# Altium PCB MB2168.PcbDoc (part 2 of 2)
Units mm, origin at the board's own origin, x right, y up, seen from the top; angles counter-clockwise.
Board outline 43 x 47 mm, 2 copper layers (Top Layer, Bottom Layer), stack 0.996 mm thick; 88 components, 71 nets, 358 pads, 587 vias.
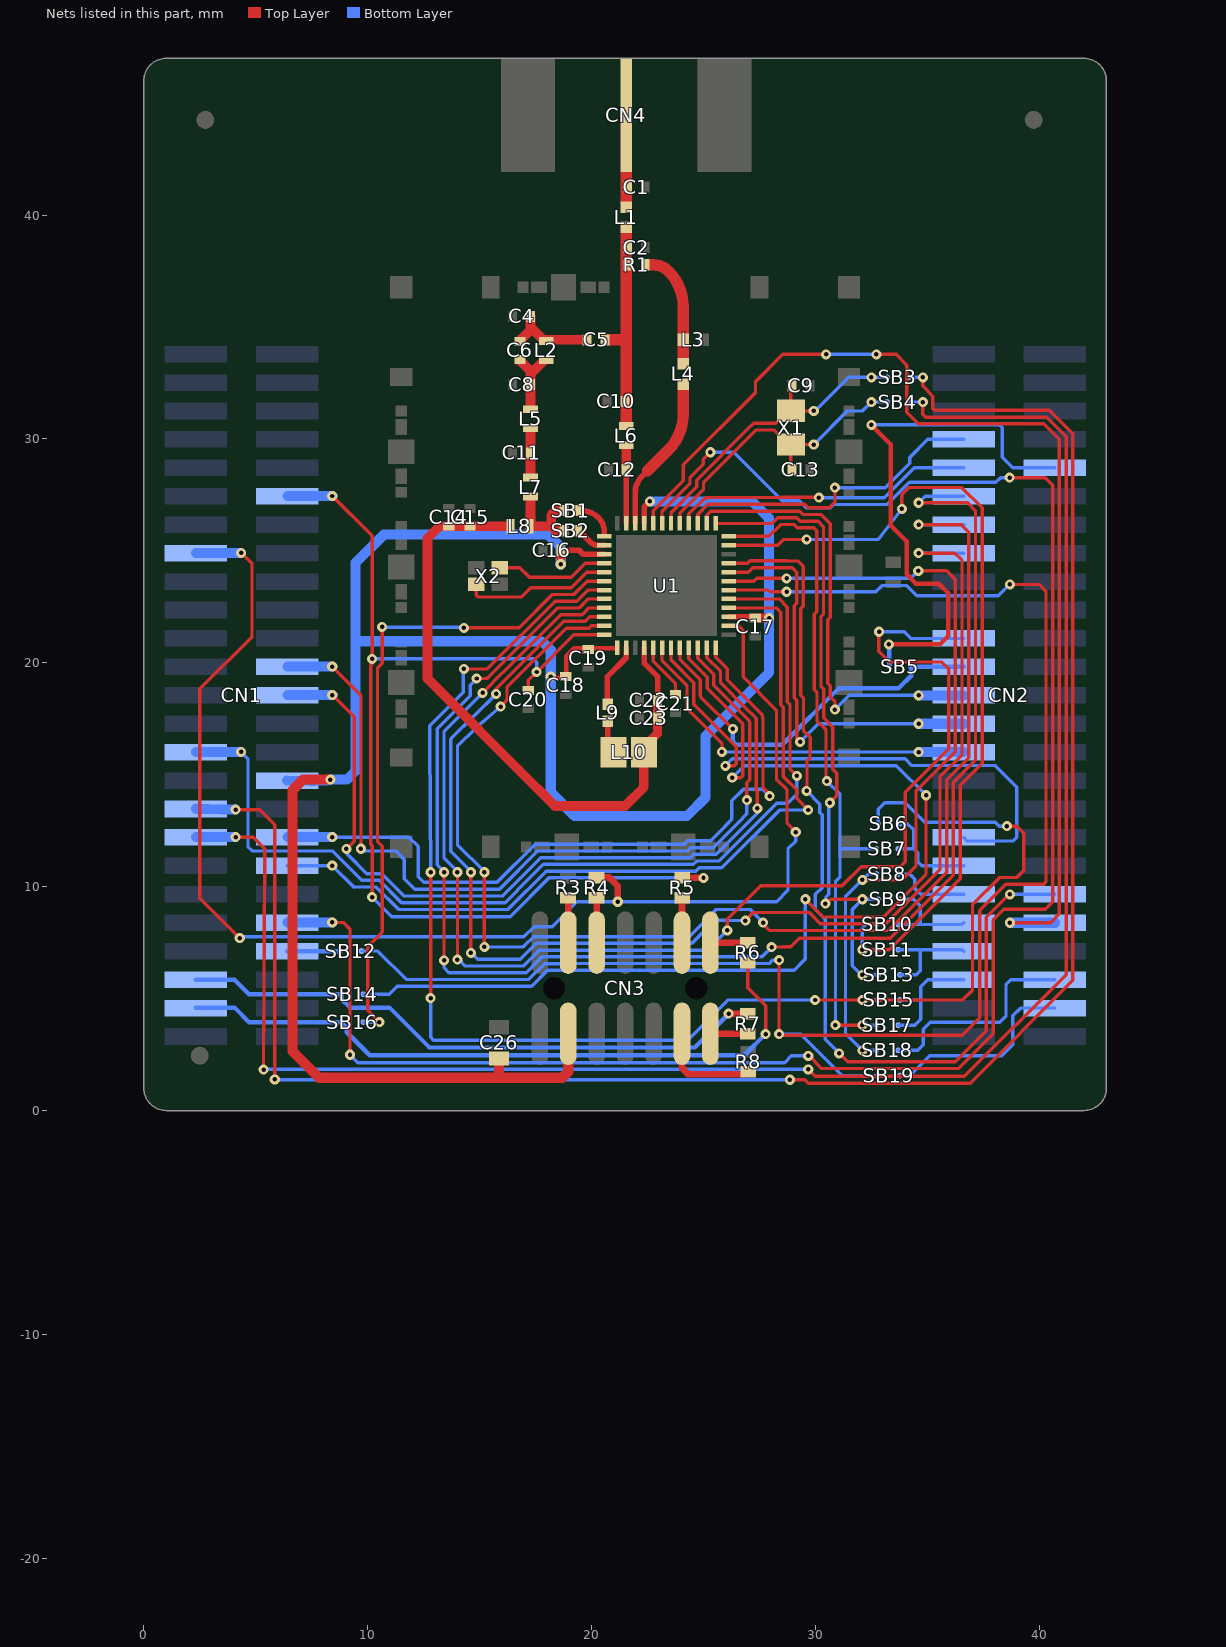
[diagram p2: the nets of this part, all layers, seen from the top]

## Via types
v1: diameter 0.45, hole 0.2, Top Layer to Bottom Layer, tented both sides, 587 vias

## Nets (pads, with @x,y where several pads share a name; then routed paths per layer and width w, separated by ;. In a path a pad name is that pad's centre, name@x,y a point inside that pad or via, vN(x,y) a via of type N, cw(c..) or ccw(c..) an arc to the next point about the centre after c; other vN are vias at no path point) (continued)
GPIO6/SWCLK: CN1.15 R4.2 U1.2 | length 61.8
  Top Layer w0.15: v1(4.287,7.7) 2.5,9.487 2.5,18.834 4.836,21.171 4.836,24.424 v1(4.35,24.91) ; U1.2@26.125,21.65 26.564,21.65 26.614,21.6 26.779,21.435 26.779,19.371 28.26,17.89 28.26,14.797 28.734,14.323 28.734,12.827 v1(29.124,12.437)
  Top Layer w0.3: R4.2@20.225,10.4 20.231,10.406 20.8,10.406 21.17,10.035 v1(21.17,9.326)
  Bottom Layer w0.15: v1(4.287,7.7) 4.299,7.712 cw(c4.405,7.605) 4.405,7.755 15.727,7.755 16.98,7.755 17.44,8.215 18.239,8.215 19.35,9.326 v1(21.17,9.326) 28.272,9.326 28.776,9.829 28.776,11.686 29.124,12.035 v1(29.124,12.437)
  Bottom Layer w0.45: CN1.15@2.343,24.91 v1(4.35,24.91)
GPIO11: CN1.24 U1.46 | length 39
  Top Layer w0.15: v1(8.42,19.83) 9.7,18.55 v1(9.7,11.695) ; U1.46@24.75,20.675 24.75,20.201 25.463,19.489 25.463,18.99 27.016,17.437 cw(c26.91,17.331) 27.06,17.331 27.06,14.768 26.935,14.643 v1(26.935,13.866)
  Bottom Layer w0.15: v1(9.7,11.695) 9.8,11.594 11.255,11.594 11.636,11.213 11.636,10.345 12.101,9.88 15.889,9.88 17.604,11.594 24.293,11.594 24.443,11.743 25.443,11.743 26.534,12.834 ccw(c26.428,12.94) 26.568,12.887 26.935,13.254 v1(26.935,13.866)
  Bottom Layer w0.45: CN1.24@6.413,19.83 v1(8.42,19.83)
GPIO12: CN1.26 U1.47 | length 38.6
  Top Layer w0.15: v1(8.42,18.56) 8.42,18.541 8.439,18.541 9.4,17.58 9.4,12.038 v1(9.05,11.688) ; U1.47@25.15,20.675 25.15,20.226 25.763,19.613 25.763,19.114 26.854,18.023 27.316,17.561 cw(c27.21,17.455) 27.36,17.455 27.36,14.293 27.406,14.248 v1(27.406,13.493)
  Bottom Layer w0.15: v1(9.05,11.688) 9.1,11.638 9.1,11.443 9.962,10.582 10.634,10.582 11.636,9.58 16.013,9.58 17.728,11.294 24.418,11.294 24.567,11.443 25.506,11.443 ccw(c25.506,11.593) 25.611,11.487 27.406,13.281 v1(27.406,13.493)
  Bottom Layer w0.45: CN1.26@6.413,18.56 v1(8.42,18.56)
GPIO14: CN1.29 U1.5 | length 45.2
  Top Layer w0.15: U1.5@26.125,22.85 28.378,22.85 28.749,22.478 28.749,18.249 28.868,18.131 28.868,15.25 v1(29.174,14.943)
  Bottom Layer w0.15: v1(4.35,16.02) 4.653,15.717 4.653,11.778 4.836,11.594 8.42,11.594 9.733,10.282 10.51,10.282 11.512,9.28 16.138,9.28 16.678,9.82 ; 16.689,9.831 17.852,10.994 24.542,10.994 24.691,11.143 25.692,11.143 28.032,13.483 28.272,13.724 28.765,13.724 29.16,14.119 29.16,14.93 v1(29.174,14.943)
  Bottom Layer w0.45: CN1.29@2.343,16.02 v1(4.35,16.02)
GPIO15/OSC32_IN: CN1.33 SB3.2 | length 86.2
  Top Layer w0.15: v1(4.101,13.437) 5.187,13.437 5.85,12.774 v1(5.85,1.39) ; v1(28.86,1.375) 29.531,1.375 29.681,1.225 36.912,1.225 41.5,5.813 41.5,30.227 40.452,31.275 35.338,31.275 35.25,31.363 35.25,31.916 34.8,32.366 v1(34.8,32.747)
  Bottom Layer w0.15: v1(5.85,1.39) 5.865,1.375 v1(28.86,1.375) v1@28.873,1.375 ; SB3.2@34.1,32.747 SB3.2@34.175,32.747 v1(34.8,32.747)
  Bottom Layer w0.45: CN1.33@2.343,13.48 3.501,13.437 v1(4.101,13.437)
GPIO16/OSC32_OUT: CN1.35 SB4.2 | length 83.1
  Top Layer w0.15: v1(4.101,12.21) 4.884,12.21 5.4,11.695 v1(5.35,1.825) ; v1(29.681,1.84) 29.996,1.525 36.65,1.525 41.2,6.075 41.2,30.102 40.327,30.975 34.932,30.975 34.8,31.107 v1(34.8,31.647)
  Bottom Layer w0.15: v1(5.35,1.825) 5.365,1.84 v1(29.681,1.84) ; SB4.2@34.1,31.647 SB4.2@34.175,31.647 v1(34.8,31.647)
  Bottom Layer w0.45: CN1.35@2.343,12.21 v1(4.101,12.21)
GPIO17: CN1.36 U1.48 | length 33.4
  Top Layer w0.15: U1.48@25.55,20.675 25.55,20.25 26.063,19.737 26.063,19.239 27.597,17.705 cw(c27.491,17.599) 27.638,17.623 27.654,17.528 cw(c27.21,17.455) 27.66,17.455 27.66,15.246 27.66,14.417 27.954,14.123 v1(27.954,14.042)
  Bottom Layer w0.15: v1(8.42,12.21) 11.84,12.21 12.254,11.796 12.254,10.439 12.5,10.193 15.778,10.193 17.479,11.894 24.15,11.894 24.299,12.043 25.319,12.043 25.975,12.699 ; v1(27.954,14.042) 27.641,14.355 26.788,14.355 26.268,13.835 26.268,13.011 26.137,12.88 ; 25.975,12.699 26.137,12.861 26.137,12.88 ; 25.975,12.699 25.975,12.718 26.137,12.88
  Bottom Layer w0.45: CN1.36@6.413,12.21 v1(8.42,12.21)
GPIO18: CN1.38 U1.4 | length 37.7
  Top Layer w0.15: U1.4@26.125,22.45 28.25,22.45 28.449,22.251 28.449,18.125 28.56,18.014 28.56,14.921 29.16,14.321 29.16,13.94 v1(29.677,13.424)
  Bottom Layer w0.15: CN1.38@6.413,10.94 v1(8.42,10.94) 9.39,9.97 9.401,9.982 10.385,9.982 11.387,8.98 16.262,8.98 17.976,10.694 24.666,10.694 24.815,10.843 25.753,10.843 ccw(c25.753,10.993) 25.858,10.886 25.901,10.929 ccw(c25.692,11.143) 25.904,10.931 28.397,13.424 v1(29.677,13.424)
GPIO21: CN1.42 U1.19 | length 86.2
  Top Layer w0.15: v1(8.42,8.4) 8.91,8.4 9.211,8.099 v1(9.211,2.491) ; U1.19@23.15,26.225 23.15,26.766 24.4,28.016 24.4,28.285 24.994,28.879 24.994,29.091 v1(25.306,29.404) ; v1(29.681,2.44) 29.717,2.44 30.283,1.875 36.375,1.875 37.938,3.438 37.938,8.513 38.413,8.988 40.261,8.988 40.6,9.326 40.6,27.932 40.259,28.273 v1(38.672,28.273)
  Bottom Layer w0.15: v1(9.211,2.491) 9.561,2.14 28.621,2.14 28.921,2.44 v1(29.681,2.44) ; v1(25.306,29.404) 26.36,29.404 28.518,27.246 29.271,27.246 29.592,26.925 30.663,26.925 30.809,27.071 33.21,27.071 34.201,28.062 38.059,28.062 38.269,28.273 v1(38.672,28.273)
  Bottom Layer w0.45: CN1.42@6.413,8.4 v1(8.42,8.4)
GPIO22: CN1.44 SB12.2 | length 2.4
  Bottom Layer w0.2: CN1.44@6.401,7.118 6.408,7.125 SB12.2@8.75,7.125
GPIO23/VCP1_RX: CN1.45 R7.1 SB14.1 | length 26.7
  Top Layer w0.3: v1(26.125,4.325) R7.1@26.975,4.325
  Bottom Layer w0.2: CN1.45@2.331,5.848 4.052,5.848 4.7,5.2 SB14.1@8.825,5.2 8.835,5.19 8.835,4.974 9.211,4.598 10.523,4.598 10.525,4.6 10.975,4.6 12.76,2.815 24.615,2.815 v1(26.125,4.325)
GPIO24/VCP1_TX: CN1.47 R6.2 SB16.1 | length 30.4
  Top Layer w0.15: R6.2@26.975,6.6 26.975,5.478 27.775,4.678 v1(27.775,3.417)
  Bottom Layer w0.2: CN1.47@2.331,4.598 4.052,4.598 4.7,3.95 SB16.1@8.825,3.95 9.063,3.712 9.063,3.496 10.094,2.465 26.824,2.465 v1(27.775,3.417)
GPIO28: CN2.7 U1.15 | length 14.3
  Top Layer w0.15: U1.15@24.75,26.225 24.75,26.624 25.201,27.075 29.534,27.075 29.684,26.925 30.62,26.925 30.875,27.18 v1(30.875,27.821)
  Bottom Layer w0.15: v1(30.875,27.821) 33.111,27.821 34.21,28.921 34.21,29.17 35.018,29.978 CN2.7@36.621,29.978
GPIO29: CN2.9 U1.16 | length 13.5
  Top Layer w0.15: U1.16@24.35,26.225 24.35,26.649 25.032,27.331 ; 25.032,27.332 cw(c25.137,27.224) 25.135,27.374 25.198,27.375 cw(c25.201,27.075) 25.2,27.375 28.448,27.388 30.145,27.388 v1(30.158,27.375)
  Bottom Layer w0.15: v1(30.158,27.375) 30.162,27.371 33.085,27.371 34.422,28.708 CN2.9@36.621,28.708
GPIO30: CN2.10 SB5.1 | length 25
  Top Layer w0.2: v1(32.5,30.625) 33.358,29.767 33.358,26.139 34.075,25.422 34.075,23.952 34.491,23.536 35.51,23.536 35.926,23.119 35.926,21.184 35.564,20.823 v1(33.283,20.823)
  Bottom Layer w0.15: v1(32.5,30.625) 38.166,30.625 cw(c38.166,30.475) 38.273,30.581 38.347,30.506 38.347,29.184 38.824,28.708 CN2.10@40.691,28.708
  Bottom Layer w0.2: v1(33.283,20.823) 33.292,20.814 33.292,19.833 SB5.1@33.3,19.825
GPIO31: CN2.11 U1.32 | length 67.1
  Top Layer w0.15: v1@13.412,10.643 13.412,6.745 13.413,6.744 v1(13.413,6.706) ; v1(14.869,19.299) 15.299,19.307 ccw(c15.296,19.457) 15.384,19.337 15.394,19.343 18.5,22.45 19.463,22.45 19.863,22.85 U1.32@20.575,22.85 ; v1(28.047,7.298) 28.568,7.311 cw(c28.572,7.161) 28.572,7.311 28.9,7.311 29.289,7.7 33.352,7.7 36.164,10.512 36.164,14.653 37.151,15.639 37.151,26.8 36.801,27.15 v1(34.614,27.15)
  Bottom Layer w0.15: v1(13.412,10.643) 13.412,10.679 13.112,10.979 13.112,17.057 14.575,18.52 14.575,19.005 v1(14.869,19.299) ; v1(13.413,6.706) 13.413,6.371 13.631,6.153 17.075,6.153 17.787,6.865 27.615,6.865 v1(28.047,7.298) ; v1(34.614,27.15) 34.902,27.438 CN2.11@36.621,27.438
GPIO33: CN2.13 U1.35 | length 61.3
  Top Layer w0.15: v1(15.212,7.305) v1(15.212,10.643) ; v1(15.935,18.04) 16.222,18.328 16.222,18.899 18.873,21.55 19.892,21.55 19.992,21.65 U1.35@20.575,21.65 ; v1(27.669,8.395) 27.669,8.321 27.948,8.042 33.27,8.042 35.864,10.636 35.864,14.777 36.851,15.764 36.851,25.841 36.524,26.168 v1(34.614,26.168)
  Bottom Layer w0.15: v1(15.212,10.643) 15.212,10.679 14.012,11.879 14.012,16.267 14.841,17.096 ccw(c14.735,17.202) 14.843,17.098 cw(c14.951,16.993) 14.853,17.107 v1(15.935,18.04) ; v1@15.25,7.305 16.896,7.308 ccw(c16.895,7.458) 17.001,7.352 17.415,7.765 24.302,7.765 ccw(c24.302,7.915) 24.408,7.809 25.578,8.98 27.085,8.98 v1(27.669,8.395) ; v1(34.614,26.168) CN2.13@36.621,26.168
GPIO34: CN2.15 U1.34 | length 60.6
  Top Layer w0.15: v1(14.612,7.043) v1(14.612,10.643) ; v1(15.736,18.606) 15.736,18.837 18.749,21.85 19.725,21.85 19.925,22.05 U1.34@20.575,22.05 ; v1(26.869,8.488) 27.227,8.845 29.718,8.845 30.221,8.342 33.084,8.342 ccw(c33.084,8.492) 33.19,8.386 35.564,10.761 35.564,14.901 36.551,15.888 36.551,24.57 36.222,24.898 v1(34.614,24.898)
  Bottom Layer w0.15: v1(14.612,10.643) 14.612,10.679 13.712,11.579 13.712,16.542 cw(c13.863,16.542) 13.757,16.649 v1(15.736,18.606) ; v1@14.692,7.043 14.692,6.984 14.917,6.759 15.276,6.759 15.282,6.753 16.827,6.753 17.539,7.465 24.488,7.465 25.515,8.492 26.125,8.492 26.13,8.488 v1(26.869,8.488) ; v1(34.614,24.898) CN2.15@36.621,24.898
GPIO37: CN2.21 U1.33 | length 59.8
  Top Layer w0.15: v1(14.012,6.744) v1(14.012,10.643) ; v1(15.138,18.658) 15.138,18.663 16.019,19.544 ; 16.024,19.55 18.624,22.15 19.587,22.15 19.888,22.45 U1.33@20.575,22.45 ; v1(26.063,8.042) 26.063,8.541 27.557,10.035 31.188,10.035 32.044,10.891 33.788,10.891 34.012,11.115 34.012,14.214 35.951,16.152 35.951,19.728 35.646,20.033 33.367,20.033 cw(c33.367,20.183) 33.244,20.097 32.833,20.508 32.833,21.373 v1(32.848,21.388)
  Bottom Layer w0.15: v1(14.012,10.643) 14.012,10.679 13.412,11.279 13.412,16.933 v1(15.138,18.658) ; v1@14.083,6.744 14.083,6.73 14.359,6.453 15.112,6.453 15.118,6.459 ccw(c15.158,6.603) 15.158,6.453 16.951,6.453 17.663,7.165 25.186,7.165 v1(26.063,8.042) ; v1(32.848,21.388) 33.965,21.388 34.265,21.088 CN2.21@36.621,21.088
GPIO39: CN2.23 SB5.2 U1.44 | length 17.2
  Top Layer w0.15: U1.44@23.95,20.675 23.95,20.15 24.26,19.84 24.263,19.84 24.7,19.403 24.7,19.4 24.863,19.237 24.863,18.552 ccw(c25.013,18.552) 24.907,18.445 v1(26.31,17.052)
  Bottom Layer w0.2: v1(26.31,17.052) 26.31,16.47 26.44,16.34 28.521,16.34 31.054,18.873 33.725,18.873 34.275,19.423 SB5.2@34.275,19.818 ; SB5.2@34.275,19.825 SB5.2@34.275,19.818 ; CN2.23@36.621,19.818 SB5.2@34.275,19.818
GPIO41: CN2.25 U1.14 | length 20.7
  Top Layer w0.15: U1.14@25.15,26.225 25.15,26.599 25.326,26.775 29.295,26.775 29.445,26.625 30.241,26.625 30.66,26.206 30.66,22.037 30.549,21.926 30.549,19.086 30.67,18.965 30.67,18.482 30.875,18.277 v1(30.875,17.907)
  Bottom Layer w0.15: v1(30.875,17.907) 31.516,18.548 v1(34.614,18.548)
  Bottom Layer w0.45: v1(34.614,18.548) CN2.25@36.621,18.548
GPIO42: CN2.27 U1.8 | length 18.6
  Top Layer w0.15: U1.8@26.125,24.05 26.992,24.05 27.192,24.25 28.61,24.25 28.611,24.248 28.962,24.248 29.16,24.05 29.16,22.665 29.049,22.554 29.049,18.434 29.168,18.315 29.168,16.615 v1(29.318,16.465)
  Bottom Layer w0.15: v1(29.318,16.465) 30.131,17.278 v1(34.614,17.278)
  Bottom Layer w0.45: v1(34.614,17.278) CN2.27@36.621,17.278
GPIO44: CN2.29 U1.42 | length 16.6
  Top Layer w0.15: U1.42@23.15,20.675 23.15,20.101 24.263,18.989 24.263,17.965 25.825,16.403 v1(25.825,16.022)
  Bottom Layer w0.15: v1(25.825,16.022) 25.832,16.015 34.607,16.015 v1(34.614,16.008)
  Bottom Layer w0.45: v1(34.614,16.008) CN2.29@36.621,16.008
GPIO47: CN2.35 U1.43 | length 25.3
  Top Layer w0.15: U1.43@23.55,20.675 23.55,20.126 24.563,19.113 24.563,18.153 26.46,16.256 26.46,15.483 26.372,15.395 v1(25.979,15.395)
  Bottom Layer w0.15: v1(25.979,15.395) 26.292,15.708 34.016,15.708 34.314,15.41 38.032,15.41 39,14.442 39,12.214 38.824,12.037 36.782,12.037 CN2.35@36.621,12.198
GPIO49: CN2.37 SB6.2 SB7.1 | length 5
  Bottom Layer w0.15: SB6.2@33.7,12.812 34.114,12.812 34.394,12.532 34.394,11.688 ; SB7.1@33.775,11.688 34.394,11.688 ; CN2.37@36.621,10.928 34.757,10.928 34.569,11.115 34.569,11.512 34.394,11.688
GPIO50: CN2.39 SB8.1 | length 3.5
  Bottom Layer w0.15: SB8.1@33.7,10.563 34.21,10.563 34.275,10.498 34.439,10.334 34.439,9.918 34.699,9.658 CN2.39@36.621,9.658
GPIO51: CN2.40 U1.9 | length 42.2
  Top Layer w0.15: U1.9@26.125,24.45 26.968,24.45 27.068,24.55 28.734,24.55 28.736,24.548 29.222,24.548 29.46,24.31 29.46,22.536 29.349,22.425 29.349,18.558 29.468,18.44 29.468,16.964 29.768,16.664 29.768,16.064 29.76,16.056 29.76,15.762 29.624,15.626 29.624,14.293 v1(29.61,14.279) ; v1(31.056,2.556) 31.394,2.218 ccw(c31.5,2.325) 31.499,2.175 36.251,2.175 37.638,3.562 37.638,8.637 38.659,9.658 v1(38.684,9.658)
  Bottom Layer w0.15: v1(29.61,14.279) 30.2,13.689 30.2,13.308 30.3,13.208 30.3,9.958 30,9.658 30,8.981 30.439,8.542 30.439,3.174 v1(31.056,2.556) ; v1(38.684,9.658) CN2.40@40.691,9.658
GPIO52: CN2.41 SB9.2 SB10.1 | length 4.8
  Bottom Layer w0.15: SB10.1@33.7,8.313 34.687,8.313 ; SB9.2@33.775,9.437 34.394,9.437 34.687,9.144 34.687,8.313 ; CN2.41@36.621,8.388 36.546,8.313 34.687,8.313
GPIO53: CN2.42 U1.20 | length 50.8
  Top Layer w0.15: U1.20@22.75,26.225 22.75,26.79 24.1,28.14 24.1,28.848 27.282,32.029 ; v1(30.475,33.775) 28.539,33.775 27.325,32.561 27.325,32.135 ; v1(32.725,33.775) 33.613,33.775 34.087,33.3 34.087,31.182 34.594,30.675 40.203,30.675 40.9,29.978 40.9,8.779 40.509,8.388 v1(38.684,8.388) ; 27.282,32.029 ccw(c27.175,32.135) 27.325,32.135 ; 27.282,32.029 27.325,32.073 27.325,32.135
  Bottom Layer w0.15: v1(30.475,33.775) v1(32.725,33.775)
  Bottom Layer w0.45: v1(38.684,8.388) CN2.42@40.691,8.388
GPIO54: CN2.43 SB11.1 SB13.2 | length 4.9
  Bottom Layer w0.15: SB11.1@33.7,7.187 34.7,7.187 ; SB13.2@33.775,6.062 34.513,6.062 34.687,6.237 34.687,7.175 34.7,7.187 ; CN2.43@36.621,7.118 36.552,7.187 34.7,7.187
GPIO55: CN2.45 SB15.2 SB17.1 | length 5.5
  Bottom Layer w0.15: SB17.1@33.7,3.812 34.439,3.812 34.7,4.073 34.7,4.95 ; SB15.2@33.775,4.938 34.687,4.938 34.7,4.95 ; CN2.45@36.621,5.848 35.018,5.848 34.7,5.53 34.7,4.95
GPIO56: CN2.46 SB18.1 | length 9.5
  Bottom Layer w0.15: SB18.1@33.7,2.688 34.569,2.688 34.813,2.931 34.813,3.637 35.125,3.95 38.237,3.95 38.517,4.23 38.517,5.642 38.723,5.848 CN2.46@40.691,5.848
GPIO57: CN2.48 SB19.2 | length 8.9
  Bottom Layer w0.15: SB19.2@33.775,1.562 34.218,1.562 35.106,2.45 38.325,2.45 38.817,2.942 38.817,4.233 39.162,4.578 CN2.48@40.691,4.578
NetC1_2: C1.2 CN4.1 L1.2 | length 4.1
  Top Layer w0.51: L1.2@21.55,40.35 21.55,41.25 CN4.1@21.55,44.46
NetC2_2: C2.2 C5.1 C10.2 L1.1 L6.2 R1.2 | length 9.6
  Top Layer w0.51: C5.1@20.65,34.425 21.55,34.425 ; L6.2@21.55,30.701 21.55,34.425 ; 21.55,37.274 21.55,34.425 ; 21.55,37.275 21.55,37.775 L1.1@21.55,39.45
NetC4_2: C4.2 C5.2 C6.2 L2.2 | length 3.9
  Top Layer w0.43: C6.2@16.8,34.4 16.825,34.4 16.865,34.44 16.865,34.465 17.275,34.875 C4.2@17.275,35.475 ; 17.337,34.937 17.85,34.425 C5.2@19.75,34.425
NetC6_1: C6.1 C8.2 L2.1 L5.2 | length 3.1
  Top Layer w0.43: C6.1@16.8,33.5 16.825,33.5 16.865,33.46 16.865,33.435 17.275,33.025 C8.2@17.275,32.425 L5.2@17.275,31.375 ; 17.337,32.963 L2.1@17.85,33.475
NetC9_2: C9.2 SB3.1 U1.18 X1.2 | length 14.1
  Top Layer w0.15: U1.18@23.55,26.225 23.55,26.704 24.7,27.854 24.7,28.161 26.988,30.448 27.239,30.7 28.237,30.7 28.35,30.813 28.35,30.825 28.775,31.25 X1.2@28.9,31.25 ; C9.2@28.9,32.375 X1.2@28.9,31.25 ; v1@30.075,31.25 X1.2@28.9,31.25
  Bottom Layer w0.15: v1(29.925,31.25) 30,31.25 31.497,32.747 v1(32.5,32.747) SB3.1@33.2,32.747
NetC11_2: C11.2 L5.1 L7.2 | length 2.1
  Top Layer w0.43: L7.2@17.275,28.325 C11.2@17.275,29.375 L5.1@17.275,30.425
NetC12_2: C12.2 L6.1 U1.23 | length 3.4
  Top Layer w0.25: U1.23@21.55,26.225 C12.2@21.55,28.625
  Top Layer w0.43: C12.2@21.55,28.625 L6.1@21.55,29.675
NetC13_2: C13.2 SB4.1 U1.17 X1.1 | length 13.6
  Top Layer w0.15: U1.17@23.95,26.225 23.95,26.68 25,27.73 25,28.036 27.364,30.4 28.149,30.4 28.35,30.199 28.35,30.175 28.775,29.75 X1.1@28.9,29.75 ; C13.2@28.9,28.625 X1.1@28.9,29.75 ; v1(29.925,29.75) X1.1@28.9,29.75
  Bottom Layer w0.15: v1(29.925,29.75) 31.422,31.247 32.1,31.247 v1(32.5,31.647) SB4.1@33.2,31.647
NetC21_2: C21.2 U1.41 | length 2.5
  Top Layer w0.15: U1.41@22.75,20.675 22.75,20.077 23.75,19.077 C21.2@23.75,18.625
NetCN3_4: CN3.4 R3.1 | length 2
  Top Layer w0.3: R3.1@18.95,9.5 18.96,9.49 CN3.4@18.96,7.5
NetCN3_6: CN3.6 R4.1 | length 2
  Top Layer w0.3: R4.1@20.225,9.5 20.23,9.495 CN3.6@20.23,7.5
NetCN3_11: CN3.11 R8.2 | length 4.7
  Top Layer w0.3: CN3.11@24.04,3.43 24.04,1.897 24.312,1.625 26.903,1.625 R8.2@27.003,1.725 ; R8.2@26.914,1.814 R8.2@26.928,1.828
NetCN3_12: CN3.12 R5.1 | length 2
  Top Layer w0.3: CN3.12@24.04,7.5 24.04,9.49 R5.1@24.05,9.5
NetCN3_13: CN3.13 R7.2 | length 1.7
  Top Layer w0.3: CN3.13@25.31,3.43 25.315,3.425 R7.2@26.975,3.425
NetCN3_14: CN3.14 R6.1 | length 1.7
  Top Layer w0.3: CN3.14@25.31,7.5 R6.1@26.975,7.5
NetL3_1: L3.1 L4.2 R1.1 | length 5.2
  Top Layer w0.51: 22.608,37.775 22.766,37.775 cw(c22.766,36.836) 23.43,37.5 cw(c21.813,35.883) 24.1,35.883 L3.1@24.1,34.425 L4.2@24.1,33.375
NetL4_1: L4.1 U1.22 | length 6.9
  Top Layer w0.25: U1.22@21.95,26.225 21.95,27.601 cw(c22.974,27.601) 22.25,28.325 22.5,28.575
  Top Layer w0.51: 22.5,28.575 23.43,29.505 ccw(c21.813,31.122) 24.1,31.122 L4.1@24.1,32.425
NetL7_1: L7.1 L8.2 SB1.2 SB2.2 | length 3.9
  Top Layer w0.43: L7.1@17.275,27.375 17.275,26.1 18.193,26.1 ; SB2.2@18.697,25.9 18.393,25.9 18.193,26.1 ; SB1.2@18.717,26.8 18.401,26.8 18.193,26.592 18.193,26.1
NetL9_1: L9.1 U1.38 | length 2.9
  Top Layer w0.25: L9.1@20.725,18.152 20.707,18.17 20.707,19.382 21.55,20.225 U1.38@21.55,20.675
NetL9_2: L9.2 L10.2 | length 1.5
  Top Layer w0.25: L9.2@20.725,17.394 20.725,16.27 L10.2@20.987,16.008
NetSB1_1: SB1.1 U1.25 | length 1.8
  Top Layer w0.25: SB1.1@19.375,26.8 19.528,26.8 cw(c19.528,25.69) 20.312,26.475 cw(c19.679,25.841) 20.575,25.841 U1.25@20.575,25.741
NetSB2_1: SB2.1 U1.26 | length 1.4
  Top Layer w0.25: SB2.1@19.375,25.9 cw(c19.375,25.746) 19.484,25.855 19.945,25.394 ccw(c20.292,25.74) 20.292,25.25 U1.26@20.575,25.25
NetSB6_1: SB6.1 SB15.1 U1.31 | length 67
  Top Layer w0.15: v1(12.812,5.025) v1(12.812,10.643) ; v1(14.301,19.725) 15.351,19.725 18.376,22.75 19.339,22.75 19.839,23.25 U1.31@20.575,23.25 ; v1(29.989,4.938) 32.033,4.923 ccw(c32.036,5.073) v1(32.1,4.938) ; v1(32.1,4.938) 36.593,4.938 37.017,5.361 37.017,9.192 38.234,10.409 39,10.409 39.312,10.722 39.312,12.386 39,12.699 38.551,12.699 v1(38.55,12.7)
  Bottom Layer w0.15: v1(12.812,5.025) 12.812,3.269 12.941,3.14 24.304,3.14 26.101,4.938 v1(29.989,4.938) ; v1(12.812,10.643) 12.781,16.461 12.781,17.181 14.275,18.675 14.275,19.699 v1(14.301,19.725) ; v1(32.1,4.938) SB15.1@32.8,4.938 ; SB6.1@32.8,12.812 32.8,13.45 33.1,13.75 34.007,13.75 34.884,12.873 38.029,12.873 38.202,12.7 v1(38.55,12.7)
NetSB7_2: SB7.2 SB17.2 U1.12 | length 30.4
  Top Layer w0.15: U1.12@26.125,25.65 27.924,25.65 28.449,26.175 29.047,26.175 29.197,26.025 29.935,26.025 30.06,25.9 30.06,22.288 29.949,22.177 29.949,18.807 30.07,18.686 30.07,17.411 30.431,17.05 cw(c30.325,16.944) 30.475,16.944 30.475,14.749 v1(30.51,14.714) ; v1(30.892,3.814) v1(32.1,3.812)
  Bottom Layer w0.15: v1(30.51,14.714) 31.1,14.124 31.1,11.688 ; v1(30.892,3.814) 30.9,3.822 30.9,10.234 31.1,10.434 31.1,11.688 ; v1(32.1,3.812) SB17.2@32.725,3.812 ; SB7.2@32.725,11.688 31.1,11.688
NetSB8_2: SB8.2 SB18.2 U1.7 | length 36.3
  Top Layer w0.15: U1.7@26.125,23.65 27.251,23.65 27.375,23.774 v1(28.71,23.774) ; v1(32.1,10.3) 33.882,10.3 34.492,10.91 34.492,14.269 36.251,16.028 36.251,23.721 35.867,24.105 v1(34.594,24.105)
  Bottom Layer w0.15: v1(28.71,23.774) 34.264,23.774 v1(34.594,24.105) ; SB18.2@32.725,2.688 v1(32.1,2.688) 31.342,3.445 31.342,9.542 v1(32.1,10.3) 32.363,10.563 SB8.2@32.725,10.563
NetSB9_1: SB9.1 SB13.1 U1.13 | length 29.4
  Top Layer w0.15: U1.13@25.55,26.225 28.075,26.225 28.325,26.475 29.171,26.475 29.321,26.325 30.117,26.325 30.36,26.082 30.36,22.161 30.249,22.05 30.249,18.942 30.37,18.821 30.37,17.535 30.775,17.13 30.775,15.25 30.96,15.064 30.96,14.06 v1(30.65,13.75) ; v1(30.45,9.244) 30.488,9.244 30.681,9.437 v1(32.1,9.437)
  Bottom Layer w0.15: v1(30.45,9.244) 30.476,9.27 30.476,9.544 30.6,9.669 30.6,13.699 v1(30.65,13.75) ; SB13.1@32.8,6.062 v1(32.1,6.062) 32.055,6.062 31.642,6.476 31.642,8.98 v1(32.1,9.437) SB9.1@32.8,9.437
NetSB10_2: SB10.2 SB11.2 U1.11 | length 38.2
  Top Layer w0.15: U1.11@26.125,25.25 28.329,25.25 28.588,25.508 v1(29.61,25.508) ; v1(32.1,7.18) 33.295,7.18 36.464,10.349 36.464,14.529 37.451,15.515 37.451,26.924 36.547,27.828 34.176,27.828 33.86,27.512 v1(33.86,26.875)
  Bottom Layer w0.15: v1(29.61,25.508) 32.735,25.508 ccw(c32.735,25.658) 32.853,25.567 v1(33.86,26.875) ; SB11.2@32.725,7.187 32.721,7.184 32.104,7.184 v1(32.1,7.18) 32.1,8.137 32.275,8.313 SB10.2@32.725,8.313
NetSB12_1: SB12.1 SB19.1 U1.6 | length 73.4
  Top Layer w0.15: U1.6@26.125,23.25 27.897,23.25 27.973,23.174 v1(28.71,23.174) ; v1(28.375,6.715) v1(28.375,3.417) 28.429,3.363 36.55,3.363 37.338,4.15 37.338,8.948 38.498,10.108 40.197,10.108 40.3,10.211 40.3,23.193 39.993,23.5 v1(38.687,23.5)
  Bottom Layer w0.15: SB12.1@9.725,7.125 10.449,7.125 11.721,5.853 17.2,5.853 17.909,6.562 19.074,6.562 19.077,6.565 27.935,6.565 28.075,6.706 v1@28.3,6.715 ; v1(28.375,3.417) 29.341,3.417 31.195,1.562 SB19.1@32.8,1.562 ; v1(28.71,23.174) 32.699,23.174 32.975,23.45 34.075,23.45 34.538,22.988 38.175,22.988 v1(38.687,23.5)
NetSB14_2: SB14.2 U1.45 | length 49.8
  Top Layer w0.15: U1.45@24.35,20.675 24.35,20.177 25.163,19.364 25.163,18.866 26.76,17.268 26.76,14.956 26.672,14.868 v1(26.287,14.868) ; v1(29.55,9.437) 30.345,8.642 33.021,8.642 34.942,10.563 v1(34.942,14.083)
  Bottom Layer w0.15: SB14.2@9.8,5.2 10.975,5.2 11.325,5.55 17.321,5.55 18.033,6.262 21.37,6.262 21.373,6.265 29.047,6.265 29.55,6.769 v1(29.55,9.437) ; v1(26.287,14.868) 26.826,15.408 27.399,15.408 33.617,15.408 v1(34.942,14.083)
NetSB16_2: SB16.2 U1.30 | length 29.8
  Top Layer w0.15: v1(10.525,3.95) 10,4.475 10,7.311 10.605,7.916 ccw(c10.499,8.023) 10.649,8.023 10.649,11.806 10.442,12.013 10.442,19.782 10.649,19.989 v1(10.649,21.6) ; v1(14.301,21.562) 16.764,21.562 18.252,23.05 19.215,23.05 19.815,23.65 U1.30@20.575,23.65
  Bottom Layer w0.15: SB16.2@9.8,3.95 v1(10.525,3.95) ; v1(10.649,21.6) 10.668,21.581 14.282,21.581 v1(14.301,21.562)
NetU1_28: U1.28 X2.3 | length 5.1
  Top Layer w0.15: X2.3@15.905,24.25 16.797,24.25 17.229,23.818 19.091,23.818 19.723,24.45 U1.28@20.575,24.45
NetU1_29: U1.29 X2.1 | length 6.7
  Top Layer w0.15: X2.1@14.855,23.5 14.855,23.025 14.943,22.938 16.866,22.938 17.279,23.35 19.09,23.35 19.79,24.05 U1.29@20.575,24.05
NRST: C20.2 CN1.12 R5.2 U1.36 | length 50.3
  Top Layer w0.15: v1(8.42,27.45) 10.155,25.715 ; 10.156,25.714 cw(c10.048,25.609) 10.198,25.609 10.199,20.938 v1(10.199,20.175) 10.199,19.963 10.142,19.906 10.142,11.889 10.199,11.832 v1(10.199,9.532) ; C20.2@17.172,18.802 17.172,19.213 v1(17.547,19.588) 19.209,21.25 U1.36@20.575,21.25
  Top Layer w0.3: R5.2@24.25,10.505 R5.2@24.05,10.4 24.053,10.397 24.998,10.397 v1(25.002,10.393)
  Bottom Layer w0.15: v1(10.199,9.532) 11.075,8.655 16.362,8.655 18.101,10.394 23.85,10.394 v1(25.002,10.393) ; v1(10.199,20.175) 11.829,20.175 ; 11.83,20.175 11.856,20.175 ccw(c11.858,20.325) 11.859,20.175 11.885,20.175 ; 11.886,20.175 17.397,20.175 17.547,20.025 v1(17.547,19.588)
  Bottom Layer w0.45: CN1.12@6.413,27.45 v1(8.42,27.45)
VDD: C16.2 C17.2 C18.2 C19.2 C26.2 CN1.32 CN3.3 U1.3 U1.21 U1.27 U1.37 | length 104.2
  Top Layer w0.2: v1(18.18,19.379) 18.192,19.285 cw(c18.316,19.161) 18.316,19.336 18.695,19.336 18.853,19.339 C18.2@18.875,19.339 ; C18.2@18.875,19.34 18.875,20.296 19.23,20.65 21.15,20.65 U1.37@21.15,20.675
  Top Layer w0.25: C16.2@18.624,25.025 19.45,25.025 19.625,24.85 U1.27@20.575,24.85 ; U1.21@22.35,26.225 22.35,26.956 v1(22.603,27.208) ; U1.3@26.125,22.05 27.185,22.05 C17.2@27.31,22
  Top Layer w0.3: v1@27.895,22 27.935,21.96 v1(27.935,22)
  Top Layer w0.4: v1(18.624,24.4) C16.2@18.624,25.025 ; C17.2@27.31,22 v1@27.895,22
  Top Layer w0.45: v1(8.338,14.778) 7.105,14.778 6.65,14.323 6.65,13.584 6.65,2.64 7.825,1.465 15.875,1.465 ; C26.2@15.875,2.325 15.875,1.465 ; CN3.3@18.96,3.43 18.96,1.733 18.692,1.465 15.875,1.465
  Bottom Layer w0.45: CN1.32@6.401,14.738 7.503,14.712 ccw(c7.509,15.012) CN1.32@7.63,14.738 ; CN1.32@7.63,14.75 8.179,14.75 ccw(c8.179,15.05) 8.244,14.757 v1(8.338,14.778) 9.078,14.778 9.461,15.161 9.461,20.962 ; v1(18.624,24.4) 18.624,25.167 18.067,25.725 10.717,25.725 9.461,24.47 9.461,20.962 ; v1(22.603,27.208) 27.178,27.208 27.926,26.461 v1(27.935,22) 27.935,19.568 25.1,16.733 25.1,13.994 24.264,13.159 19.233,13.159 18.18,14.212 v1(18.18,19.379) 18.18,20.57 17.876,20.874 ccw(c17.664,20.662) 17.664,20.962 9.461,20.962
VFBSD: C14.1 C15.2 C22.2 C23.1 L8.1 L10.1 U1.40 | length 29
  Top Layer w0.25: U1.40@22.35,20.675 22.35,19.982 22.951,19.381 22.951,18.322 C22.2@22.95,18.321
  Top Layer w0.4: L10.1@22.376,16.275 22.95,16.85 C22.2@22.95,18.321
  Top Layer w0.43: L8.1@16.325,26.1 C15.2@14.575,26.1 C14.1@13.625,26.1 13.21,26.1 12.674,25.564 12.674,19.29 13.227,18.737 16.749,15.215 18.363,13.601 21.5,13.601 22.339,14.439 L10.1@22.339,16.008
pads on no net: CART-1.1 CN1.2 CN1.3 CN1.4 CN1.5 CN1.8 CN1.10 CN1.11 CN1.16 CN1.18 CN1.19 CN1.20 CN1.21 CN1.23 CN1.27 CN1.30 CN1.39 CN1.41 CN1.43 CN1.48 CN1.50 CN2.1 CN2.3 CN2.4 CN2.5 CN2.6 CN2.12 CN2.16 CN2.17 CN2.18 CN2.19 CN2.22 CN2.24 CN2.28 CN2.30 CN2.31 CN2.33 CN2.34 CN2.36 CN2.47 CN2.49 CN3.1 CN3.2 CN3.8 CN3.9 CN3.10 CN3.NPTH1 CN3.NPTH2 MIRE-1.1 MIRE-2.1 MIRE-3.1 MIRE-4.1 MIRE-5.1

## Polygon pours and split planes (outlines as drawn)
GND on Top Layer "GND_L01_P001" (solid, remove dead copper, pour order 1): 0,47 43,47 43,0 0,0
GND on Top Layer "GND_L01_P004" (solid, remove dead copper, pour order 4): 14.496,29.375 14.5,29.371 14.5,27.35 14.787,27.063 16.625,27.063 16.625,29.375
GND on Bottom Layer "GND_L02_P003" (solid, remove dead copper, pour order 3): 0,47 43,47 43,0 0,0

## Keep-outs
Top Layer:
  region: 21.207,31.141 19.559,31.141 cw(c19.559,31.675) 19.025,31.675 cw(c19.55,31.675) 19.55,32.2 21.207,32.2
  region: 16.625,34.941 15.284,34.941 cw(c15.284,35.475) 14.75,35.475 cw(c15.275,35.475) 15.275,36 16.625,36 16.625,35.85
  region: 22,28.091 19.559,28.091 cw(c19.559,28.625) 19.025,28.625 cw(c19.55,28.625) 19.55,29.15 22,29.15
  region: 14.155,23.87 14.08,23.87 cw(c14.08,24.25) 13.7,24.25 cw(c14.075,24.25) 14.075,24.625 15.225,24.625 15.225,23.875
  region: 13.091,26.75 13.091,28.091 cw(c13.625,28.091) 13.625,28.625 cw(c13.625,28.1) 14.15,28.1 14.15,26.75 14,26.75
  region: 17.275,31.891 15.284,31.891 cw(c15.284,32.425) 14.75,32.425 cw(c15.275,32.425) 15.275,32.95 17.275,32.95
  region: 17.275,28.841 15.284,28.841 cw(c15.284,29.375) 14.75,29.375 cw(c15.275,29.375) 15.275,29.9 17.275,29.9
  region: 14.041,26.75 14.041,28.091 cw(c14.575,28.091) 14.575,28.625 cw(c14.575,28.1) 15.1,28.1 15.1,26.75 14.95,26.75
  region: 25.3,34.959 26.091,34.959 cw(c26.091,34.425) 26.625,34.425 cw(c26.1,34.425) 26.1,33.9 25.3,33.9
  region: 15.954,24.804 19.448,24.804 19.448,25.74 15.954,25.74

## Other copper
Top Layer:
  rectangle net GND: 20.679,29.15 21.075,29.4
  rectangle net GND: 20.7,30.858 21.17,31.141
  rectangle net GND: 24.48,33.4 24.98,33.891
  pour cut-out: 21.55,37.395 22.766,37.395 cw(c22.766,36.836) 23.161,37.231 23.162,37.23 cw(c21.813,35.883) 23.72,35.883 23.72,32.855 24.48,32.855 24.48,35.883 ccw(c21.813,35.883) 23.699,37.769 ccw(c22.766,36.836) 22.766,38.155 21.55,38.155
  pour cut-out: 22,30.858 21.17,30.858 21.083,30.858 21.083,29.15 22,29.15
  pour cut-out: 18.14,18.401 16,18.402 16,19.411 18.156,19.434
  pour cut-out: 19.423,17.403 19.423,15.072 24.25,15.072 24.25,17.369
  pour cut-out: 18.14,18.754 19.509,18.754 19.509,16.172 18.14,16.172
  region net GND: 22.351,18.663 21.207,18.663 21.207,17.063 22.35,17.063
  pour cut-out: 19.448,34.855 21.17,34.855 21.17,33.995 19.448,33.995
  pour cut-out: 21.17,30.575 21.17,47 21.931,47 21.931,30.575
  pour cut-out: 13.865,24.825 13.617,24.577 13.617,23.738 14.647,22.708 15.261,22.708 15.261,24.823
  pour cut-out: 28.5,32.938 28.588,33.025 30.193,33.025 30.309,32.909 30.309,28.089 30.313,28.085 30.29,28.062 28.128,28.062 27.924,28.266 27.924,32.362

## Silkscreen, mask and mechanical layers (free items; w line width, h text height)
Top Overlay:
  lines w0.12: 19.75,25.975 20,26.225 20,26.546 20.354,26.9 22.527,26.9
  text "J" at 31.675,41.686 h10
  text "MB2168A" at 30.963,39.013 h2.3
  text "H" at 7.912,38.4 h10
  text "K" at 2.052,38.289 h8
  text "RX_WAKEUP" at 24.9,37.74 h1.3
  text "E" at 7.539,6.607 h9
  text "C" at 1.36,6.215 h8
  text "I" at 36.886,3.613 h10
M1-Board Shape:
  the board outline again, w0.1
Drill Drawing:
  drawing of 166 lines, arcs and shapes, not listed
  text "PCB SPECIFICATIONS :" at -22.541,97.137 h3
  text "TG-150" at 51.675,93.175 h3
  text "A.   MATERIAL :" at -22.541,93.137 h3
  text "FR-4" at 15.959,93.137 h3
  text "TG-170" at 32.459,93.137 h3
  text "X   TG-140" at 66.1,93.1 h3
  text "B.   MATERIAL FAMILY :" at -22.541,90.137 h3
  text "Ventec VT-47" at 15.959,90.137 h3
  text "C.   SOLDERMASK COLOR :" at -22.541,87.137 h3
  text "GREEN" at 15.959,87.137 h3
  text "X  BLUE" at 32.459,87.137 h3
  text "RED" at 50.709,87.137 h3
  text "BLACK" at 66.709,87.137 h3
  text "D.   SILKSCREEN COLOR :" at -22.541,84.137 h3
  text "X  WHITE" at 15.959,84.137 h3
  text "YELLOW" at 32.459,84.137 h3
  text "BLACK" at 50.709,84.137 h3
  text "E.   SURFACE FINISH :" at -22.541,81.137 h3
  text "X  ENIG" at 15.959,81.137 h3
  text "IMMERSION SILVER" at 32.459,81.137 h3
  text "IMMERSION TIN" at 66.709,81.137 h3
  text "HASL" at 15.959,78.137 h3
  text "HASL (PB-FREE)" at 32.459,78.137 h3
  text "GOLDEN FINGER" at 66.709,78.137 h3
  text "F.   IMPEDANCE CONTROL :" at -22.541,75.137 h3
  text "NO" at 15.959,75.137 h3
  text "X  YES" at 32.459,75.137 h3
  text "G.   THROUGH VIA :" at -22.541,72.137 h3
  text "PLUG THE VIAS WHICH ARE COVERED WITH SOLDERMASK ONE OR TWO SIDE." at 15.959,72.137 h3
  text "PLUG MATERIAL :" at 15.959,69.137 h3
  text "X  SOLDERMASK" at 41.459,69.137 h3
  text "NON-CONDUCTIVE EPOXY." at 66.709,69.137 h3
  text "H.   STACK-UP :" at -22.541,66.137 h3
  text "SEE LAYER STACK-UP SEQUENCE FOR OVERALL THICKNESS." at 15.959,66.137 h3
  text "PCB : TYPE 3" at 110.088,57.996 h3
  text "ASPECT-RATIO, AXE Z :" at 110.088,52.496 h3
  text "6 :1 à 8 :1 / LEVEL \"B\"" at 110.107,45.749 h3
  text "Layer" at 50.841,44.7 h1.8
  text "Name" at 58.372,44.7 h1.8
  text "Material" at 72.928,44.7 h1.8
  text "Thickness" at 86.013,44.7 h1.8
  text "Constant" at 96.758,44.7 h1.8
  text "Top Overlay" at 58.372,41.1 h1.8
  text "Top Solder" at 58.372,37.5 h1.8
  text "Solder Resist" at 72.928,37.5 h1.8
  text "0.010mm" at 86.013,37.5 h1.8
  text "3.5" at 96.758,37.5 h1.8
  text "1" at 50.841,33.9 h1.8
  text "Top Layer" at 58.372,33.9 h1.8
  text "Copper" at 72.928,33.9 h1.8
  text "0.041mm" at 86.013,33.9 h1.8
  text "MINIMUN PARAMETERS" at 109.5,32.02 h3
  text "Dielectric 2" at 58.372,30.3 h1.8
  text "FR4" at 72.928,30.3 h1.8
  text "0.914mm" at 86.013,30.3 h1.8
  text "4.3" at 96.758,30.3 h1.8
  text "2" at 50.84,26.7 h1.8
  text "Bottom Layer" at 58.372,26.7 h1.8
  text "Copper" at 72.928,26.7 h1.8
  text "0.041mm" at 86.013,26.7 h1.8
  text "DEFAULT" at 109.5,26.52 h3
  text "Bottom Solder" at 58.372,23.1 h1.8
  text "Solder Resist" at 72.928,23.1 h1.8
  text "0.010mm" at 86.013,23.1 h1.8
  text "3.5" at 96.758,23.1 h1.8
  text "TRACKS : 0.150mm           / GAPS : 0.150mm" at 109.5,20.77 h3
  text "Bottom Overlay" at 58.372,19.5 h1.8
  text "Symbol" at 51.124,12.705 h2.16
  text "Count" at 59.578,12.705 h2.16
  text "Hole Size" at 68.346,12.705 h2.16
  text "Plated" at 83.766,12.705 h2.16
  text "Hole Type" at 91.191,12.705 h2.16
  text "Drill Layer Pair" at 101.995,12.705 h2.16
  text "Via/Pad" at 122.464,12.705 h2.16
  text "Hole Length" at 131.319,12.705 h2.16
  text "587" at 59.578,8.977 h1.8
  text "0.20mm (7.87mil)" at 68.346,8.977 h1.8
  text "PTH" at 83.766,8.977 h1.8
  text "Round" at 91.191,8.977 h1.8
  text "Top Layer - Bottom Layer" at 101.995,8.977 h1.8
  text "Via" at 122.464,8.977 h1.8
  text "-" at 131.319,8.977 h1.8
  text "2" at 59.578,5.249 h1.8
  text "1.00mm (39.37mil)" at 68.346,5.249 h1.8
  text "NPTH" at 83.766,5.249 h1.8
  text "Round" at 91.191,5.249 h1.8
  text "Top Layer - Bottom Layer" at 101.995,5.249 h1.8
  text "Pad" at 122.464,5.249 h1.8
  text "-" at 131.319,5.249 h1.8
  text "589 Total" at 59.578,1.522 h1.8

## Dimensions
1,0 to 1,47 on M2-Board Dimensions
0,1 to 43,1 on M2-Board Dimensions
